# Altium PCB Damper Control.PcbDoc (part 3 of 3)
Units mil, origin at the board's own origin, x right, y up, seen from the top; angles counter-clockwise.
Board outline 4586.61 x 2962.6 mil, 4 copper layers (Top Layer, GND Plane, Power Plane, Bottom Layer), stack 70.356 mil thick; 195 components, 143 nets, 589 pads, 854 vias.
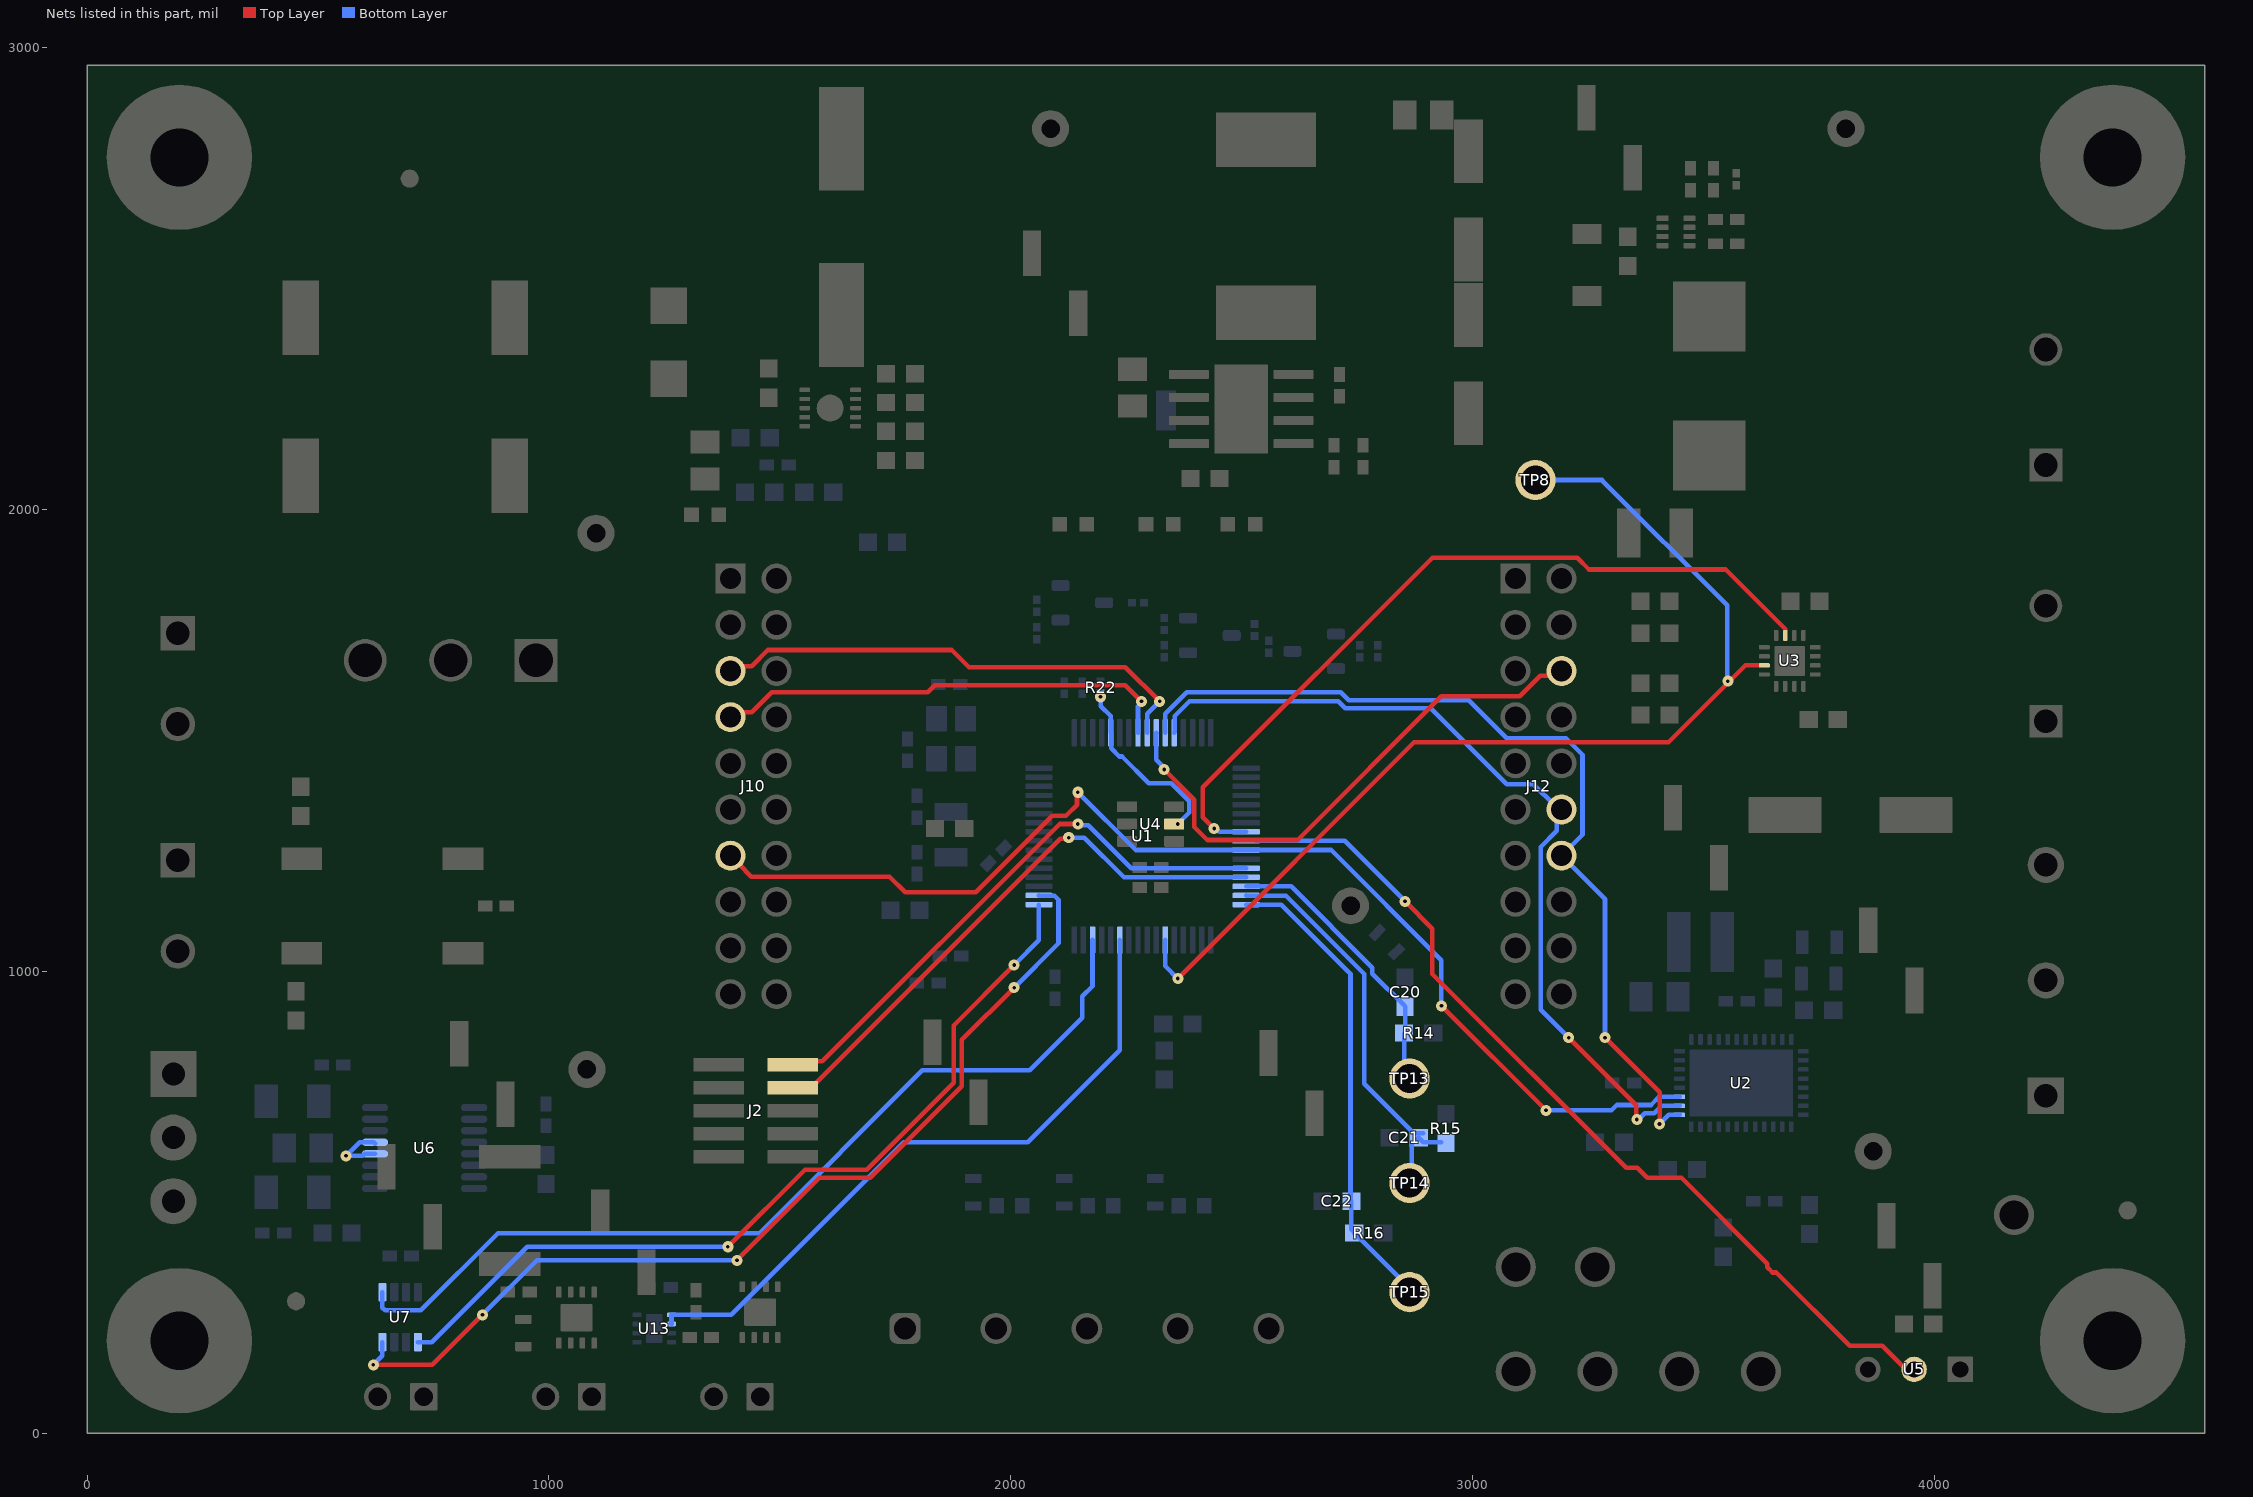
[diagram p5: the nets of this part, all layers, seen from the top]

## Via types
v1: diameter 12, hole 6, Top Layer to Bottom Layer, tented both sides, 463 vias
v2: diameter 24, hole 8, Top Layer to Bottom Layer, tented both sides, 202 vias
v3: diameter 12, hole 6, Top Layer to Bottom Layer, 145 vias
v4: diameter 19.68, hole 7.87, Top Layer to Bottom Layer, 19 vias
v5: diameter 19.68, hole 7.87, Top Layer to Bottom Layer, tented both sides, 16 vias
v6: diameter 24.8, hole 12.99, Top Layer to Bottom Layer, 7 vias
v7: diameter 20, hole 8, Top Layer to Bottom Layer, tented both sides, 1 vias
v8: diameter 24, hole 8, Top Layer to Bottom Layer, 1 vias

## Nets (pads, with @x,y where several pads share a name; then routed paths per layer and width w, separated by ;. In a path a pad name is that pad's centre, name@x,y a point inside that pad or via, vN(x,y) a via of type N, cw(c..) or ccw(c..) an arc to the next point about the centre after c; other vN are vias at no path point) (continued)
S_GND: U6.12 U6.13 | length 140.4
  Bottom Layer w10: U6.13@620.08,629.79 590.42,629.79 v2(561.02,600.39) 597.03,600.39 601.43,604.79 U6.12@623.65,604.79 ; U6.13@620.08,629.92 620.86,629.92 U6.13@623.65,627.13
SHDN: U1.33 U7.5 | length 1853.9
  Top Layer w10: v2(1387.8,403.54) 1554.84,570.59 1688.62,570.59 1876.75,758.72 1876.75,882.65 v2(2007.87,1013.78)
  Bottom Layer w10: U7.5@716.54,196.85 746.56,196.85 953.25,403.54 v2@1387.43,403.54 ; v2@2008.57,1014.48 2061.43,1067.33 U1.33@2061.43,1144.49
SOA: C20.1 R14.2 TP13.1 U1.14 | length 594.9
  Bottom Layer w10: U1.14@2510.25,1183.86 2607.46,1183.86 2783.62,1007.69 2783.62,994.92 C20.1@2853.35,925.2 ; R14.2@2852.36,866.14 2852.36,803.19 2858.31,797.24 TP13.1@2864.17,797.24 ; TP13.1@2854.33,767.72 TP13.1@2856.36,769.75 ; R14.2@2854.33,866.14 C20.1@2854.33,923.23
SOB: C21.1 R15.2 TP14.1 U1.15 | length 897.7
  Bottom Layer w10: U1.15@2510.25,1164.17 2511.15,1163.27 2596.58,1163.27 2765.75,994.09 2765.75,756.89 2873.03,649.61 C21.1@2893.7,649.61 ; TP14.1@2852.55,551.18 TP14.1@2864.17,551.18 ; TP14.1@2874.02,551.18 2869.17,556.02 2869.17,626.06 2882.87,639.76 C21.1@2883.86,639.76 2893.7,629.92 R15.2@2933.07,629.92
SOC: C22.1 R16.2 TP15.1 U1.16 | length 1031.4
  Bottom Layer w10: U1.16@2510.25,1144.49 2585.83,1144.49 2731.3,999.02 2736.22,994.09 C22.1@2736.22,501.97 ; C22.1@2738.19,501.97 2738.19,440.94 R16.2@2746.06,433.07 ; R16.2@2744.09,433.07 2745.08,433.07 2863.19,314.96 TP15.1@2874.02,314.96
SPI1_CLK: J10.13 U1.10 U2.35 | length 2537.2
  Top Layer w10: J10.13@1397.64,1230.32 1399.76,1232.44 1411.26,1232.44 1438.66,1205.04 1737.87,1205.04 1771.65,1171.26 1924.94,1171.26 2090.45,1336.77 2119.98,1336.77 2144,1360.8 2144,1386.13 v2(2145.67,1387.8) ; v2(2933.07,925.2) v2(3159.45,698.82)
  Bottom Layer w10: v2(2145.67,1387.8) 2270.87,1262.6 U1.10@2510.25,1262.6 2694.1,1262.6 2933.07,1023.62 v2(2933.07,925.2) ; v2(3159.45,698.82) 3301.44,698.82 3313.09,710.47 3386.92,710.47 3404.79,728.35 U2.35@3448.82,728.35
SPI1_CS: J12.6 U1.58 | length 1203
  Top Layer w10: v2(2332.68,1437.01) 2398.2,1371.49 2398.2,1312.43 2426.45,1284.18 2621.43,1284.18 2933,1595.75 3102.8,1595.75 3146.93,1639.88 3175.31,1639.88 J12.6@3188.98,1653.54 ; J12.6@3208.66,1653.54 J12.6@3210.24,1651.97
  Bottom Layer w10: U1.58@2316.27,1515.63 U1.58@2315.36,1516.53 2315.36,1457.88 2332.68,1440.57 v2(2332.68,1437.01) ; J12.6@3188.98,1653.54 J12.6@3188.98,1654.72 ; J12.6@3198.82,1653.54 J12.6@3201.97,1650.39
SPI1_MISO: J12.14 U1.59 U2.33 | length 1978
  Top Layer w10: v2(3287.4,856.3) 3405.51,738.19 v2(3405.51,669.29)
  Bottom Layer w10: U1.59@2335.05,1516.53 2335.05,1557.49 2381.89,1604.33 2715.38,1604.33 2732.54,1587.17 2992.39,1587.17 3074.52,1505.04 3202.8,1505.04 3238.66,1469.18 3238.66,1295.75 J12.14@3193.31,1250.39 3287.4,1156.3 v2(3287.4,856.3) ; v2(3405.51,669.29) 3425.2,688.98 U2.33@3448.82,688.98
SPI1_MOSI: J12.12 U1.60 U2.34 | length 1864.4
  Top Layer w10: v2(3208.66,856.3) 3355.04,709.92 3355.04,680.39 v2(3356.3,679.13)
  Bottom Layer w10: U1.60@2354.73,1516.53 2355.64,1517.44 2355.64,1552.8 2387.48,1584.65 2709.78,1584.65 2725.14,1569.29 2910.27,1569.29 3074.52,1405.04 3132.36,1405.04 3179.13,1358.27 J12.12@3188.98,1358.27 ; J12.12@3198.82,1348.43 3195.28,1348.43 J12.12@3193.31,1350.39 3182.79,1339.88 3182.79,1304.02 3147.95,1269.18 3147.95,917.01 v2(3208.66,856.3) ; v2(3356.3,679.13) 3360.09,679.13 3373.55,692.6 3394.32,692.6 3410.39,708.66 U2.34@3448.82,708.66
STB: U1.34 U7.8 | length 2120.6
  Top Layer w10: v2(620.08,147.64) 748.03,147.64 v2(856.3,255.91) ; v2(1407.48,374.02) 1586.18,552.72 1696.02,552.72 1894.62,751.31 1894.62,851.32 v2(2007.87,964.57)
  Bottom Layer w10: v2(620.08,147.64) 639.76,167.32 U7.8@639.76,196.85 ; v2(856.3,255.91) 974.41,374.02 v2(1407.48,374.02) v2@1409.91,374.02 ; v2(2007.87,964.57) 2103.83,1060.52 2103.83,1154.58 2095.15,1163.27 2062.33,1163.27 U1.34@2061.43,1164.17
STEP: TP8.1 U1.22 U3.11 | length 2331.5
  Top Layer w10: v2(2362.2,984.25) 2873.7,1495.75 3424.88,1495.75 3591.53,1662.4 U3.11@3625.46,1662.4
  Bottom Layer w10: U1.22@2335.05,1067.71 2335.05,1011.41 v2(2362.2,984.25) ; TP8.1@3136.51,2063.8 3280.69,2063.8 3551.84,1792.65 3551.84,1629.65 v2(3553.25,1628.24)
STEP_VREF: U1.8 U3.7 | length 1717.1
  Top Layer w10: v2(2440.95,1309.06) 2416.07,1333.93 2416.07,1398.1 2913.72,1895.75 3227.04,1895.75 3252.71,1870.08 3548.72,1870.08 3677.55,1741.25 U3.7@3677.55,1727.36
  Bottom Layer w10: v2(2440.95,1309.06) 2444.73,1309.06 2451.82,1301.97 U1.8@2510.25,1301.97
TCLK: J2.4 U1.13 | length 1214.9
  Top Layer w10: J2.4@1555.12,748.03 1568.7,748.03 2107.36,1286.69 2123.31,1286.69 v2(2125.98,1289.37)
  Bottom Layer w10: v2(2125.98,1289.37) 2159.76,1289.37 2245.59,1203.54 U1.13@2510.25,1203.54
TMAG_INT: R22.1 U1.53 U4.5 | length 407.6
  Bottom Layer w10: R22.1@2194.88,1604.33 2195.44,1603.77 2195.44,1574.24 2216.94,1552.75 U1.53@2216.94,1516.53 2217.84,1515.63 2217.84,1482.81 2235.6,1465.06 2241.37,1465.06 2298.96,1407.48 2348.17,1407.48 2387.08,1368.57 2387.08,1343.77 v2(2362.2,1318.9)
  other v2: 2194.88,1594.49
TMP_IN: U1.9 U5.2 | length 1974.7
  Top Layer w10: v2@2853.36,1152.55 v2(2854.33,1151.57) 2913.39,1092.52 2913.39,994.15 3333.05,574.49 3356.93,574.49 3378.42,552.99 3452.91,552.99 3639,366.91 3639,358.72 3650.06,347.66 3658.24,347.66 3817.07,188.83 3887.87,188.83 3956.69,120 U5.2@3956.69,118.11
  Bottom Layer w10: U1.9@2529.53,1283.19 2530.43,1282.28 2723.62,1282.28 v2(2854.33,1151.57)
TMS: J2.2 U1.12 | length 1237.3
  Top Layer w10: J2.2@1528.35,798.03 1535.15,804.84 1592.24,804.84 2106.3,1318.9 v2(2145.67,1318.9)
  Bottom Layer w10: v2(2145.67,1318.9) 2148.35,1316.22 2168.09,1316.22 2261.08,1223.23 U1.12@2510.25,1223.23
TXD: U1.30 U7.1 | length 1991.5
  Bottom Layer w10: U7.1@639.76,305.12 639.76,271.61 645.62,265.75 722.77,265.75 890.1,433.07 1456.69,433.07 1809.03,785.41 2041.39,785.41 2155.51,899.54 2155.51,946.02 2177.57,968.08 U1.30@2177.57,1067.71
UART_RX: J10.5 U1.57 | length 1077.9
  Top Layer w10: J10.5@1387.8,1653.54 1395.16,1660.91 1439.68,1660.91 1474.52,1695.75 1873.05,1695.75 1910.07,1658.73 2248.75,1658.73 v2(2322.83,1584.65)
  Bottom Layer w10: U1.57@2295.68,1516.53 2295.68,1557.49 v2(2322.83,1584.65)
UART_TX: J10.7 U1.56 | length 1009.1
  Top Layer w10: J10.7@1387.8,1555.12 1393.59,1560.91 1439.68,1560.91 1483.1,1604.33 1820.87,1604.33 1835.9,1619.36 2248.75,1619.36 v2(2283.46,1584.65)
  Bottom Layer w10: U1.56@2276.9,1517.44 U1.56@2275.99,1516.53 2275.99,1573.39 2283.46,1580.86 v2(2283.46,1584.65)
V_Ctrl: U1.27 U13.1 U13.2 | length 1468.5
  Bottom Layer w10: U13.2@1265.75,236.22 U13.1@1265.75,255.83 ; U13.1@1265.75,255.91 1395.04,255.91 1769.06,629.92 2037.4,629.92 2125.98,718.5 ; 2124.57,717.09 2236.62,829.14 U1.27@2236.62,1067.71
pads on no net: FID1.1 FID2.1 FID3.1 H2.0 H3.1 H5.0 H6.1 H8.0 H9.1 H11.0 H12.1 J2.6 J2.8 J10.3 J10.6 J10.8 J10.9 J10.10 J10.11 J10.12 J10.14 J10.15 J10.16 J10.18 J10.20 J12.1 J12.3 J12.4 J12.5 J12.7 J12.8 J12.9 J12.10 J12.11 J12.13 J12.15 J12.16 J12.18 J12.20 U1.21 U1.47 U1.54 U1.61 U2.1 U2.24 U6.6 U6.7 U8.6 U9.1 U9.2 U11.9 U12.9 U13.9@1228.35,208.66 U13.9@1228.35,244.09
copper on no net:
  other v4: 1060.04,230.32 1457.68,242.13 1035.43,250 1084.65,250 1433.07,261.81 1482.28,261.81 1060.04,269.68 1457.68,281.5

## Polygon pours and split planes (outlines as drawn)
NetC31_2 on Bottom Layer "BOTTOM_LAYER_NETC31_2_P001" (solid, remove dead copper, pour order 1): 2372.05,2263.78 2363.57,2263.78 2204.72,2263.78 2204.72,2322.83 2076.77,2322.83 2076.77,2125.98 2372.05,2125.98
GND on Bottom Layer "BOTTOM_LAYER_GND_P119" (solid, remove dead copper, pour order 119): -27.96,2927.62 -27.96,4.39 -47.65,-15.29 -27.96,-34.98 4568.49,-34.98 4568.49,2917.78 4558.65,2927.62
NetL1_1 on Bottom Layer "BOTTOM_LAYER_NETL1_1_P073" (solid, remove dead copper, pour order 73): 3515.59,954.72 3614.02,954.72 3614.02,1029.69 3622.05,1029.69 3622.05,1147.8 3515.59,1147.8 3515.59,990.32
5V on Bottom Layer "BOTTOM_LAYER_5V_P076" (solid, remove dead copper, pour order 76): 3484.25,905.51 3484.25,1151.57 3395.67,1151.57 3395.67,994.09 3405.51,994.09 3405.51,885.83 3503.94,885.83 3503.94,905.51
OUTB on Bottom Layer "BOTTOM_LAYER_OUTB_P003" (solid, remove dead copper, pour order 3): 4576.77,1082.68 4576.77,836.61 4183.07,836.61 4084.65,738.19 3710.63,738.19 3710.63,787.4 4005.91,787.4 4222.44,1082.68
NetC29_1 on Bottom Layer "BOTTOM_LAYER_NETC29_1_P005" (solid, remove dead copper, pour order 5): 816.93,688.98 816.93,669.29 885.83,669.29 885.83,659.45 964.57,659.45 964.57,580.71 1013.78,580.71 1013.78,688.98 935.04,688.98 935.04,718.5 875.98,718.5 875.98,688.98
Line on Bottom Layer "BOTTOM_LAYER_LINE_P011" (solid, remove dead copper, pour order 11): 9.84,1574.8 521.65,1574.8 521.65,1830.71 501.97,1850.39 9.84,1850.39
Neutral on Bottom Layer "BOTTOM_LAYER_NEUTRAL_P031" (solid, remove dead copper, pour order 31): 9.84,1574.8 521.65,1574.8 521.65,1328.74 9.84,1328.74
EFuse_IN on Bottom Layer "BOTTOM_LAYER_EFUSE_IN_P051" (solid, remove dead copper, pour order 51): 1387.95,2193.43 1387.95,2017.88 1387.8,2017.72 1338.58,2017.72 1338.58,1958.66 1456.69,1958.66 1456.69,2066.93 1446.85,2066.93 1446.85,2253.94 1387.8,2253.94
F_IN1 on Bottom Layer "BOTTOM_LAYER_F_IN1_P052" (solid, remove dead copper, pour order 52): 111.73,838.73 108.27,835.27 108.27,718.5 305.12,718.5 305.12,659.45 413.39,659.45 413.39,767.72 413.39,836.61 118.11,836.61
F_IN2 on Bottom Layer "BOTTOM_LAYER_F_IN2_P053" (solid, remove dead copper, pour order 53): 108.27,698.82 108.27,690.17 108.27,580.71 265.75,580.71 265.75,472.44 413.39,472.44 413.39,561.02 354.33,561.02 354.33,659.45 295.28,659.45 295.28,718.5 108.27,718.5
NetC12_2 on Bottom Layer "Bottom Layer-NetC12_2" (solid, remove dead copper, pour order 54): 3622.05,836.61 3681.1,836.61 3681.1,875.98 3759.84,875.98 3759.84,1033.46 3986.22,1033.46 3986.22,1279.53 3631.89,1279.53 3631.89,984.25 3681.1,984.25 3681.1,905.51 3651.57,905.51 3651.57,885.83 3622.05,885.83
OUTA on Bottom Layer "BOTTOM_LAYER_OUTA_P055" (solid, remove dead copper, pour order 55): 4576.77,1348.43 4084.65,1348.43 4084.65,1141.73 3986.22,1141.73 3986.22,846.46 3710.63,846.46 3710.63,797.24 4005.91,797.24 4291.34,1082.68 4576.77,1082.68
F_GND on Bottom Layer "BOTTOM_LAYER_F_GND_P096" (solid, remove dead copper, pour order 96): 76.51,849.79 78.74,847.56 78.74,378.94 688.98,378.94 688.98,418.31 688.98,880.91 78.74,880.91
NetC4_1 on Bottom Layer "BOTTOM_LAYER_NETC4_1_P090" (solid, remove dead copper, pour order 90): 2012.8,1264.76 1968.5,1309.06 1924.21,1264.76 1968.5,1220.47
PGND on Bottom Layer "BOTTOM_LAYER_PGND_P081" (solid, remove dead copper, pour order 81): 3681.1,1092.52 3897.64,1092.52 3897.64,846.46 3681.1,846.46
OUTC on Bottom Layer "BOTTOM_LAYER_OUTC_P056" (solid, remove dead copper, pour order 56): 4576.77,836.61 4576.77,590.55 4084.65,590.55 4015.75,659.45 3710.63,659.45 3710.63,728.35 4074.8,728.35 4183.07,836.61
GND on Top Layer "TOP_LAYER_GND_P124" (solid, remove dead copper, pour order 124): 0,2972.44 9.84,2962.6 4586.61,2962.6 4586.61,2470.47 3730.32,2470.47 3720.47,2480.32 3602.36,2480.32 3602.36,2588.58 3592.52,2598.43 3582.68,2588.58 3444.88,2588.58 3444.88,2529.53 3405.51,2529.53 3405.51,2490.16 3297.24,2490.16 3297.24,2293.31 3730.32,2293.31 3730.32,2470.47 4586.61,2470.47 4586.61,0 4576.77,-9.84 0,-9.84
EFuse_IN on Top Layer "TOP_LAYER_EFUSE_IN_P008" (solid, remove dead copper, pour order 8): 716.69,1548.48 872.78,1548.48 875.98,1545.28 875.98,1811.02 1309.06,1811.02 1309.06,2175.2 1476.38,2175.2 1525.59,2224.41 1564.96,2224.41 1564.96,2273.62 1358.27,2273.62 1358.27,2352.36 1141.73,2352.36 1141.73,2234.25 19.68,2234.25 19.68,1840.55 718.5,1840.55
Line on Top Layer "TOP_LAYER_LINE_P043" (solid, remove dead copper, pour order 43): 29.53,1131.89 639.76,1131.89 639.76,935.04 29.53,935.04
Neutral on Top Layer "TOP_LAYER_NEUTRAL_P064" (solid, remove dead copper, pour order 64): 29.53,1368.11 639.76,1368.11 639.76,1141.73 29.53,1141.73
NetC35_1 on Top Layer "TOP_LAYER_NETC35_1_P067" (solid, remove dead copper, pour order 67): 649.61,1102.36 649.61,954.72 1033.46,954.72 1033.46,964.57 1033.46,1801.18 885.83,1801.18 885.83,1102.36
24VDC_IN on Top Layer "TOP_LAYER_24VDC_IN_P068" (solid, remove dead copper, pour order 68): 39.37,1830.71 39.37,1614.17 708.66,1614.17 708.66,1830.71
15VDC on Top Layer "Top Layer-15VDC" (solid, remove dead copper, pour order 69): 2746.06,2116.14 2952.76,2116.14 2952.76,2303.15 3198.82,2303.15 3198.82,2805.12 3277.56,2805.12 3277.56,2942.91 3100.39,2942.91 3100.39,2677.17 2952.76,2677.17 2952.76,2883.86 2303.15,2883.86 2303.15,2588.58 2746.06,2588.58
NetC36_1 on Top Layer "TOP_LAYER_NETC36_1_P110" (solid, remove dead copper, pour order 110): 2440.95,2490.16 2440.95,2342.52 2568.9,2342.52 2568.9,2273.62 2736.22,2273.62 2736.22,2490.16
3V3 on Top Layer "TOP_LAYER_3V3_P101" (solid, remove dead copper, pour order 101): 629.92,629.92 629.92,531.5 708.66,531.5 708.66,629.92
NetC30_1 on Top Layer "TOP_LAYER_NETC30_1_P104" (solid, remove dead copper, pour order 104): 767.72,501.97 688.98,501.97 688.98,374.02 767.72,374.02
NetC31_2 on Top Layer "Top Layer-NetC31_2" (solid, remove dead copper, pour order 83): 1938.98,2116.14 2224.41,2116.14 2224.41,2135.83 2312.99,2135.83 2312.99,2175.2 2431.1,2175.2 2431.1,2263.78 2204.72,2263.78 2204.72,2372.05 2204.72,2618.11 2096.46,2618.11 2096.46,2431.1 2093.14,2430.78 1978.67,2430.78 1978.35,2431.1 1978.35,2332.68 1938.98,2332.68
EFuse_OUT on Top Layer "Top Layer-EFuse_OUT" (solid, remove dead copper, pour order 123): 1397.64,2253.94 1673.23,2253.94 1673.23,2322.83 1978.35,2322.83 1978.35,2431.1 2106.3,2431.1 2106.3,2618.11 1397.64,2618.11
BOUT1 on Top Layer "TOP_LAYER_BOUT1_P107" (solid, remove dead copper, pour order 107): 4576.77,2470.47 4094.49,2470.47 4094.49,2244.09 3769.69,1751.97 3769.69,1702.76 3789.37,1702.76 4291.34,2214.57 4576.77,2214.57
0_10VDC on Top Layer "TOP_LAYER_0_10VDC_P122" (solid, remove dead copper, pour order 122): 1486.22,39.37 1486.22,187.01 1505.91,187.01 1505.91,216.54 1338.58,216.54 1338.58,187.01 1427.17,187.01 1427.17,39.37
4_20mA on Top Layer "TOP_LAYER_4_20MA_P121" (solid, remove dead copper, pour order 121): 1122.05,206.69 1122.05,19.68 1053.15,19.68 1053.15,177.17 915.35,177.17 915.35,206.69
NetC26_1 on Top Layer "TOP_LAYER_NETC26_1_P120" (solid, remove dead copper, pour order 120): 2578.74,875.98 2549.21,905.51 2322.83,905.51 2244.09,984.25 2244.09,1141.73 2352.36,1141.73 2352.36,1171.26 2214.57,1171.26 2214.57,944.88 2312.99,846.46 2519.69,846.46 2519.69,797.24 2539.37,777.56 2578.74,777.56
NetC28_1 on Top Layer "TOP_LAYER_NETC28_1_P118" (solid, remove dead copper, pour order 118): 4045.28,374.02 4045.28,285.43 4084.65,285.43 4084.65,88.58 4025.59,88.58 4025.59,167.32 3976.38,167.32 3976.38,285.43 3848.43,285.43 3848.43,374.02 3858.27,374.02
AOUT1 on Top Layer "TOP_LAYER_AOUT1_P116" (solid, remove dead copper, pour order 116): 4591.05,1610.21 4586.61,1605.77 4586.61,1377.95 4074.8,1377.95 3877.95,1574.8 3818.9,1574.8 3769.69,1624.02 3769.69,1633.86 3838.58,1633.86 3838.58,1624.02 4575.59,1624.02
AOUT2 on Top Layer "TOP_LAYER_AOUT2_P115" (solid, remove dead copper, pour order 115): 4576.77,1929.13 4183.07,1929.13 4183.07,1919.29 3937.01,1673.23 3769.69,1673.23 3769.69,1633.86 3838.58,1633.86 3838.58,1624.02 4576.77,1624.02
BOUT2 on Top Layer "TOP_LAYER_BOUT2_P105" (solid, remove dead copper, pour order 105): 4576.77,2214.57 4281.5,2214.57 3799.21,1702.76 3769.69,1702.76 3769.69,1673.23 3937.01,1673.23 4192.91,1929.13 4576.77,1929.13
NetC10_2 on Top Layer "Top Layer-NetC10_2" (solid, remove dead copper, pour order 109): 3759.84,1161.42 3759.84,1559.06 3710.63,1598.43 3710.63,1628.52 3690.95,1628.52 3690.95,1574.8 3582.68,1574.8 3582.68,1289.37 3356.3,1289.37 3356.3,1161.42 3582.68,1161.42
NetC26_1 on Top Layer "TOP_LAYER_NETC26_1_P113" (solid, remove dead copper, pour order 113): 2335.23,1376.9 2332.68,1374.35 2332.68,1259.84 2312.99,1240.16 2312.99,1151.57 2352.36,1151.57 2352.36,1250 2362.2,1250 2372.05,1259.84 2372.05,1377.95 2332.68,1377.95
NetC43_1 on Top Layer "TOP_LAYER_NETC43_1_P098" (solid, remove dead copper, pour order 98): 3395.67,2559.06 3205.87,2559.06 3205.87,2834.65 3395.67,2834.65
3V3 on Top Layer "TOP_LAYER_3V3_P112" (solid, remove dead copper, pour order 112): 3297.24,2293.31 3297.24,2037.4 3395.67,2037.4 3395.67,1889.76 3720.47,1889.76 3730.32,1889.76 3730.32,2293.31
NetC46_1 on Top Layer "TOP_LAYER_NETC46_1_P085" (solid, remove dead copper, pour order 85): 3454.72,2588.58 3454.72,2519.69 3405.51,2519.69 3405.51,2490.16 3405.51,2332.68 3602.36,2332.68 3602.36,2500 3602.36,2519.69 3553.15,2519.69 3484.25,2519.69 3484.25,2588.58
NetC36_2 on Top Layer "TOP_LAYER_NETC36_2_P111" (solid, remove dead copper, pour order 111): 2568.9,2224.41 2677.17,2224.41 2736.22,2224.41 2736.22,2263.78 2568.9,2263.78
GND on Power Plane "POWER_PLANE_GND_P133" (solid, remove dead copper, pour order 133): 29.53,1840.55 29.53,2942.91 2312.99,2942.91 2312.99,2312.99 1141.73,2312.99 1141.73,2244.09 246.06,2244.09 246.06,1840.55
GND on Power Plane "POWER_PLANE_GND_P130" (solid, remove dead copper, pour order 130): 649.61,1112.2 875.98,1112.2 875.98,1545.28 708.66,1545.28 708.66,1604.33 19.68,1604.33 19.68,1377.95 649.61,1377.95
GND on Power Plane "POWER_PLANE_GND_P134" (solid, remove dead copper, pour order 134): 19.68,954.72 19.68,885.83 1328.74,885.83 1328.74,1811.02 1033.46,1811.02 1033.46,954.72
EFuse_IN on Power Plane "POWER_PLANE_EFUSE_IN_P028" (solid, remove dead copper, pour order 28): 717.5,1541.77 721.01,1545.28 875.98,1545.28 875.98,1811.02 1309.06,1811.02 1309.06,2175.2 1368.11,2175.2 1368.11,2352.36 1141.73,2352.36 1141.73,2234.25 246.06,2234.25 246.06,1840.55 718.5,1840.55
NetC35_1 on Power Plane "POWER_PLANE_NETC35_1_P132" (solid, remove dead copper, pour order 132): 649.61,1102.36 649.61,954.72 1033.46,954.72 1033.46,1801.18 885.83,1801.18 885.83,1102.36
24VDC_IN on Power Plane "POWER_PLANE_24VDC_IN_P131" (solid, remove dead copper, pour order 131): 19.68,1830.71 19.68,1614.17 708.66,1614.17 708.66,1830.71
Neutral on Power Plane "POWER_PLANE_NEUTRAL_P129" (solid, remove dead copper, pour order 129): 29.53,1368.11 29.53,1141.73 639.76,1141.73 639.76,1368.11
Line on Power Plane "POWER_PLANE_LINE_P128" (solid, remove dead copper, pour order 128): 19.68,1131.89 19.26,954.72 639.76,954.72 639.76,1131.89
3V3 on Power Plane "Power Plane-3V3" (solid, remove dead copper, pour order 127): 4586.61,0 4586.61,501.97 3769.69,501.97 3769.69,2312.99 1328.74,2312.99 1328.74,895.67 0,895.67 0,9.84 -9.84,0
NetC4_1 on Power Plane "POWER_PLANE_NETC4_1_P033" (solid, remove dead copper, pour order 33): 1781.5,1259.84 1781.5,1062.99 2032.48,1062.99 2027.43,1325.38 1929.13,1259.84
15VDC on Power Plane "Power Plane-15VDC" (solid, remove dead copper, pour order 126): 2312.99,2322.83 2746.06,2322.83 2746.06,2066.93 2982.28,2066.93 2982.28,2322.83 3750,2322.83 3750,1732.28 3257.87,1732.28 3257.87,492.13 4586.61,492.13 4586.61,2952.76 2312.99,2952.76
EFuse_OUT on Power Plane "POWER_PLANE_EFUSE_OUT_P077" (solid, remove dead copper, pour order 77): 2099.28,2622.48 2096.46,2619.66 2096.46,2322.83 1397.64,2322.83 1397.64,2637.8 2096.46,2637.8 2096.46,2618.11
GND on GND Plane "GND_PLANE_GND_P093" (solid, remove dead copper, pour order 93): 0,2972.44 0,9.84 9.84,0 4586.61,0 4586.61,2962.6
F_GND on GND Plane "GND_PLANE_F_GND_P091" (solid, remove dead copper, pour order 91): 29.53,885.83 29.53,383.86 688.98,383.86 688.98,885.83
S_GND on GND Plane "GND_PLANE_S_GND_P080" (solid, remove dead copper, pour order 80): 575.79,571.17 575.79,659.45 487.2,659.45 487.2,570.56 575.79,570.56
PGND on GND Plane "GND_PLANE_PGND_P089" (solid, remove dead copper, pour order 89): 3779.53,875.98 3681.1,875.98 3681.1,551.18 4094.49,551.18 4094.49,1033.46 3779.53,1033.46 3779.53,1023.62 3779.53,1033.46 3779.53,1023.62

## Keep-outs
Keep-Out Layer:
  text ".Layer_Name" at 577,-858.49 h60

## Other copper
Top Layer:
  pour cut-out: 2303.15,2578.74 2303.15,2362.2 2431.1,2362.2 2431.1,2500 2736.22,2500 2736.22,2578.74
  text ".Layer_Name" at 577,-858.49 h60
GND Plane:
  pour cut-out: 2017.72,1328.74 2086.61,1328.74 2086.61,1309.06 2027.56,1309.06 2017.72,1318.9
  pour cut-out: 1879.92,1161.42 2032.48,1313.98 2017.72,1328.74 1850.39,1161.42
  pour cut-out: 1988.19,1643.7 1968.5,1643.7 1968.5,1486.22 2037.4,1417.32 2037.4,1437.01 1988.19,1486.22
  pour cut-out: 1751.97,1181.1 1870.08,1181.1 1870.08,1161.42 1751.97,1161.42
  pour cut-out: 1751.97,1643.7 1751.97,1161.42 1732.28,1161.42 1732.28,1643.7
  pour cut-out: 1732.28,1643.7 1988.19,1643.7 1988.19,1663.39 1732.28,1663.39
Bottom Layer:
  pour cut-out: 1830.71,1328.74 1830.71,1279.53 1929.13,1279.53 1988.19,1338.58 1978.35,1348.43 1958.66,1328.74
  text ".Layer_Name" at 577,-858.49 h60

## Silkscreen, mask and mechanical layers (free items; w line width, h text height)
Top Overlay:
  lines w10: 1417.32,1594.49 1437.01,1614.17 1545.28,1614.17 ; 1427.17,1683.07 1446.85,1702.76 1545.28,1702.76 ; 3041.34,1082.68 3051.18,1082.68 3061.02,1072.83 ; 3228.35,1250 3287.4,1250 3297.24,1240.16 3297.24,1220.47 ; 3228.35,1368.11 3267.72,1407.48 ; 3228.35,1624.02 3267.72,1584.65 3267.72,1515.75 ; 3267.72,1417.32 3267.72,1407.48 ; 3267.72,1407.48 3267.72,1407.48
  text "TPS62932 VIN" at 3293.4,2880.02 h30
  text "GND" at 2043.4,2732.38 h30
  text "GND" at 3765.84,2732.38 h30
  text "EFuse_OUT" at 1944.98,2333.83 h30
  text "BOUT1" at 4049.12,2309.15 h30 r90
  text "BOUT2" at 4049.12,2053.24 h30 r90
  text "STEP" at 3076.87,1944.98 h30
  text "EFuse_IN" at 990.25,1861.39 h30
  text "3V3" at 1246.16,1836.71 h30
  text "5V" at 1561.12,1836.71 h30
  text "GND" at 3254.03,1836.71 h30
  text "GND" at 1561.12,1738.28 h30
  text "AOUT2" at 4049.12,1738.28 h30 r90
  text "UART_RX" at 1561.12,1674.38 h30
  text "24VDC_IN" at 412.23,1620.17 h30 r90
  text "UART_TX" at 1561.12,1595.64 h30
  text "'.PRJ_Number'.PCB_Rev" at 2007.87,1515.75 h108.27
  text "24VDC" at 547.34,1492.22 h30
  text "24VAC" at 901.67,1492.22 h30
  text "AOUT1" at 4049.12,1482.38 h30 r90
  text "SPI1_CS" at 3263.87,1477.53 h30
  text "GND" at 407.39,1472.54 h30 r90
  text "SPI1_MOSI" at 3263.87,1428.32 h30
  text "24VAC IN" at 124.11,1354.43 h30
  text "SPI1_CLK" at 1098.52,1231.47 h30
  text "SPI1_MISO" at 3263.87,1182.26 h30
  text "OUTA" at 4049.12,1157.57 h30 r90
  text "Neutral" at 397.54,1147.73 h30 r90
  text "GPIO1" at 2899.7,1068.99 h30
  text "I2C1_SCL" at 1098.52,1034.62 h30
  text "Line" at 397.54,970.57 h30 r90
  text "GPIO2" at 2899.7,950.88 h30
  text "I2C1_SDA" at 1098.52,926.35 h30
  text "OUTB" at 4049.12,921.35 h30 r90
  text "MSPM0 VDD" at 1757.97,901.67 h30
  text "TMAG VCC" at 2496.16,881.98 h30
  text "DRV8316C VM" at 3706.79,862.3 h30
  text "GND" at 1039.46,852.46 h30
  text "3V3" at 1196.94,783.56 h30
  text "TMS" at 1610.33,783.56 h30
  text "F_IN1" at 333.49,744.19 h30 r90
  text "GND" at 1196.94,734.35 h30
  text "TCLK" at 1610.33,734.35 h30
  text "ISO1212 VCC" at 557.18,685.13 h30
  text "GND" at 1196.94,685.13 h30
  text "OUTC" at 4049.12,685.13 h30 r90
  text "SOA" at 2820.96,655.61 h30
  text "GND" at 1196.94,635.92 h30
  text "GND" at 1196.94,586.71 h30
  text "RESET" at 1610.33,586.71 h30
  text "F_IN2" at 333.49,567.02 h30 r90
  text "PGND" at 3815.06,517.81 h30
  text "TLV9002 VCC" at 1147.73,488.28 h30
  text "GND" at 1738.28,458.76 h30
  text "HALLC" at 1895.76,458.76 h30
  text "HALLB" at 2092.61,458.76 h30
  text "HALLA" at 2289.46,458.76 h30
  text "3V3" at 2506,458.76 h30
  text "INLC" at 3037.5,439.07 h30
  text "INHC" at 3214.66,439.07 h30
  text "SOB" at 2820.96,429.23 h30
  text "F_GND" at 333.49,389.86 h30 r90
  text "TMP VIN" at 3628.05,370.17 h30
  text "FAULT" at 4100.49,360.33 h30
  text "TCAN VCC" at 547.34,350.49 h30
  text "SOC" at 2830.8,183.17 h30
  text "4_20mA" at 1039.46,148.79 h30
  text "0_10VDC" at 1413.48,148.79 h30
  text "CANH" at 557.18,143.8 h30
  text "CANL" at 704.82,143.8 h30
  text "GND" at 941.04,143.8 h30
  text "GND" at 1295.37,143.8 h30
  text "INLB" at 3037.5,15.84 h30
  text "INHB" at 3214.66,15.84 h30
  text "INLA" at 3391.83,15.84 h30
  text "INHA" at 3568.99,15.84 h30
  text ".Layer_Name" at 577,-858.49 h60
Bottom Overlay:
  text ".Layer_Name" at 577,-858.49 h60
Top Paste:
  text ".Layer_Name" at 577,-858.49 h60
Bottom Paste:
  text ".Layer_Name" at 577,-858.49 h60
Top Solder:
  text ".Layer_Name" at 577,-858.49 h60
  text ".Layer_Name" at 577,-858.49 h60
Bottom Solder:
  text ".Layer_Name" at 577,-858.49 h60
Drill Guide:
  text ".Layer_Name" at 577,-858.49 h60
M1 Board Outline:
  the board outline again, w10
  text ".Layer_Name" at 577,-858.49 h60
M2 Board Dimensions:
  rectangle: 0,-275 125,-150
  rectangle: 125,-400 500,-275
  lines w7: 0,-275 1000,-275 ; 125,-400 125,-150 ; 250,-400 250,-150 ; 500,-400 500,-150 ; 750,-400 750,-150 ; 0,-400 1000,-400 1000,-150 0,-150 0,-400
  text ".Layer_Name" at 577,-858.49 h60
M3 3D STEP Top:
  text ".Layer_Name" at 577,-858.49 h60
M4 3D STEP Bottom:
  text ".Layer_Name" at 577,-858.49 h60
M5 Assembly Top:
  lines w10: -292,-930.17 6308,-930.17 ; -292,-726.83 6310,-726.83 ; -292,-523.5 -292,-1133.5 3713,-1133.5 6310,-1133.5 6310,-523.5 -291.5,-523.5 -291.5,-1133.5 1284,-1133.5 ; 2173,-1133.5 2173,-523.5 ; 3440,-726.83 3440,-523.5 ; 4280,-726.83 4280,-523.5 ; 4902,-1140 4902,-937.17
  text "COMPONENTS MARKED 'DNP' SHOULD NOT BE POPULATED." at 1153.5,-318.5 h60
  text "ASSEMBLY VARIANT:" at 1153,-434 h60
  text ".VariantName" at 2189,-434 h60
  text "PCB VIEWED FROM TOP SIDE" at -228.5,-655.67 h60
  text "BOARD #:" at 2248,-655.67 h60
  text ".PRJ_Number" at 2793.5,-655.67 h60
  text "REV:" at 3638,-655.67 h60
  text ".PCB_Rev" at 3929.5,-655.67 h60
  text "SVN REV:" at 4476,-655.67 h60
  text ".VersionControl_RevNumber" at 4982,-655.67 h60
  text "TID #:" at 2248,-859 h60
  text ".TID" at 2793.5,-859 h60
  text "PLOT NAME =" at -228.5,-1064.34 h60
  text ".plot_File_Name" at 577,-1064.34 h60
  text "GENERATED    :" at 2250,-1064.34 h60
  text ".Print_Date" at 3119.5,-1064.34 h60
  text ".Print_Time" at 3848.5,-1064.34 h60
  text "TEXAS INSTRUMENTS" at 5113,-1064.34 h60
M6 Assembly Bottom:
  lines w10: -292.5,-727.33 6309.5,-727.33 ; -290.5,-930.67 6309.5,-930.67 ; 1115.5,-1140.5 1115.5,-937.67 ; 1737.5,-727.33 1737.5,-524 ; 2577.5,-727.33 2577.5,-524 ; 3844.5,-1134 3844.5,-524 ; 4733.5,-1134 6309,-1134 6309,-524 -292.5,-524 -292.5,-1134 2304.5,-1134 6309.5,-1134 6309.5,-524
  text "COMPONENTS MARKED 'DNP' SHOULD NOT BE POPULATED." at 6102,-318 h60
  text ".VariantName" at 5058,-434 h60
  text "ASSEMBLY VARIANT:" at 6097,-434 h60
  text ".VersionControl_RevNumber" at 1035.5,-656.17 h60
  text "SVN REV:" at 1541.5,-656.17 h60
  text ".PCB_Rev" at 2088,-656.17 h60
  text "REV:" at 2379.5,-656.17 h60
  text ".PRJ_Number" at 3224,-656.17 h60
  text "BOARD #:" at 3769.5,-656.17 h60
  text "PCB VIEWED FROM BOTTOM SIDE" at 6246,-656.17 h60
  text ".TID" at 3224,-859.5 h60
  text "TID #:" at 3769.5,-859.5 h60
  text "TEXAS INSTRUMENTS" at 904.5,-1064.84 h60
  text ".Print_Time" at 2169,-1064.84 h60
  text ".Print_Date" at 2898,-1064.84 h60
  text "GENERATED    :" at 3767.5,-1064.84 h60
  text ".plot_File_Name" at 5440.5,-1064.84 h60
  text "PLOT NAME =" at 6246,-1064.84 h60
M9 Title Sheet:
  drawing of 57 lines, arcs and shapes, not listed
  text "1" at 739.84,8036.5 h70
  text "2" at 3235.5,8036.5 h70
  text "3" at 5724.84,8036.5 h70
  text "4" at 8231.51,8036.5 h70
  text "5" at 10730.5,8036.5 h70
  text "6" at 13235.5,8036.5 h70
  text "A" at -416.5,6893.5 h70
  text "A" at 14383.5,6893.5 h70
  text "B" at -416.5,4513.5 h70
  text "B" at 14383.5,4513.5 h70
  text "C" at -416.5,2138.5 h70
  text "C" at 14383.5,2138.5 h70
  text "PROJECT TITLE:" at 11343.5,277.5 h45
  text ".PRJ_Title" at 11393.5,144.17 h70
  text "DESIGNED FOR:" at 11343.5,-23.5 h45
  text ".PRJ_Customer" at 11393.5,-163.5 h70
  text "D" at -416.5,-231.5 h70
  text "D" at 14383.5,-231.5 h70
  text "FILE NAME:" at 11343.5,-323.5 h45
  text ".PCB_File_Name_No_Path" at 11393.5,-443.5 h70
  text "Texas Instruments (TI) and/or its licensors do not warrant the accuracy or completeness of this specification" at 6374,-605.34 h45
  text "ENGINEER:" at 11343.5,-613.5 h45
  text "LAYOUT BY:" at 12848.5,-613.5 h45
  text "or any information contained therein. TI and/or its licensors do not warrant that this design will meet" at 6329.01,-718 h45
  text ".PRJ_Engineer" at 11393.5,-768.49 h70
  text ".PCB_Layout" at 12899,-768.49 h70
  text "the specifications, will be suitable for your application or fit for any particular purpose, or will operate in" at 6329.01,-830.67 h45
  text ".Layer_Name" at 577,-858.49 h60
  text "ALTIUM DESIGNER VERSION:" at 12848.5,-923.5 h45
  text "an implementation. TI and/or its licensors do not warrant that the design is production worthy. You should" at 6329.01,-943.33 h45
  text "completely validate and test your design implementation to confirm the system functionality for your application." at 6374,-1056 h45
  text ".print_Scale" at 11393.5,-1056.83 h70
  text ".Application_BuildNumber" at 12899,-1056.83 h70
  text "1" at 739.84,-1263.5 h70
  text "2" at 3235.5,-1263.5 h70
  text "3" at 5724.84,-1263.5 h70
  text "4" at 8231.51,-1263.5 h70
  text "5" at 10730.5,-1263.5 h70
  text "6" at 13235.5,-1263.5 h70
M10 Fab Notes:
  drawing of 189 lines, arcs and shapes, not listed
  text "DESIGN INFORMATION" at 12382.02,6356.17 h60
  text "MIN. TRACK WIDTH:" at 11737.46,6224.05 h60
  text "8" at 12833.7,6224.05 h60
  text "MIL" at 12988.46,6224.05 h60
  text "7.874" at 12667.32,6102.36 h60
  text "MIN. CLEARANCE:" at 11737.46,6099.92 h60
  text "MIL" at 12988.46,6099.92 h60
  text "MIN. VIA PAD SIZE:" at 11737.46,5975.8 h60
  text "24" at 12803.71,5975.8 h60
  text "MIL" at 12988.46,5975.8 h60
  text "0.05mm (2MIL)" at 12432.46,5845.9 h60
  text "MINIMUM ANNULAR RING" at 11408.23,5837.67 h60
  text "EXTERNAL" at 13140.46,5837.67 h60
  text "PER" at 11608.23,5727.55 h60
  text "IPC-D-275 CLASS 2 LEVEL C" at 11828.23,5727.54 h60
  text "MIL, HOLES" at 13316.46,5627.07 h60
  text "+/-" at 12924,5618.48 h60
  text "+/-" at 13778,5618.48 h60
  text "REGISTRATION TOLERANCES:" at 11408.23,5617.42 h60
  text "METAL" at 12608,5617.42 h60
  text "5" at 13184.2,5617.42 h60
  text "3" at 14017.2,5617.42 h60
  text "MIL" at 14133.46,5617.42 h60
  text "HOLE SIZE TOLERANCE (UNLESS OTHERWISE SPECIFIED):" at 11408.23,5519.1 h60
  text "+/-" at 13778,5516.23 h60
  text "3" at 14017.2,5515.17 h60
  text "MIL" at 14133.46,5515.17 h60
  text "MATERIAL:" at 11333.46,5377.52 h60
  text "FR-4 High Tg" at 12319.9,5249 h60
  text "X" at 12175.46,5241.01 h60
  text "FR-4" at 11754.46,5236.49 h60
  text "OTHER" at 13242.46,5236.49 h60
  text "62 MIL (1.6mm) +/-10%" at 12074.56,5093.46 h60
  text "X" at 11954.46,5091.01 h60
  text "THICKNESS:" at 11408.23,5085.24 h60
  text "OTHER" at 13359.46,5085.24 h60
  text "TOLERANCE:" at 11408.23,4946.92 h60
  text "X" at 12256.46,4946.92 h60
  text "ANSI IPC-6012 TYPE 3 CLASS 2" at 12434.48,4946.92 h60
  text "OTHER +/-" at 12434.46,4802.73 h60
  text "BOW & TWIST:" at 11408.23,4657.54 h60
  text "X" at 12256.46,4657.54 h60
  text "ANSI IPC-6012 TYPE 3 CLASS 2" at 12434.48,4657.54 h60
  text "OTHER +/-" at 12434.46,4510.85 h60
  text "DRILLING:" at 11333.46,4380.23 h60
  text "NC_DRILL FILES" at 13094.46,4275.04 h60
  text "REFERENCE:" at 11408.23,4271.1 h60
  text "X" at 12065.46,4271.01 h60
  text "AS SHOWN" at 12243.46,4271.1 h60
  text "X" at 12966.46,4271.1 h60
  text "OTHER" at 13392.46,4128.85 h60
  text "PTH COPPER THICKNESS:" at 11407.91,4125.32 h60
  text "X" at 12547.14,4125.32 h60
  text "20-30 um" at 12675.14,4125.32 h60
  text "BOARD FINISH:" at 11333.46,3977.73 h60
  text "SILKSCREEN:" at 11488.68,3867.6 h60
  text "X" at 12446.46,3867.6 h60
  text "TOP" at 12563.46,3867.6 h60
  text "X" at 12956.46,3867.6 h60
  text "BOTTOM" at 13074.46,3867.6 h60
  text "SILKSCREEN COLOR:" at 11488.68,3712.41 h60
  text "X" at 12445.46,3712.41 h60
  text "WHITE" at 12563.46,3712.41 h60
  text "OTHER" at 13074.46,3712.41 h60
  text "X" at 12576.46,3568.96 h60
  text "GREEN" at 12694.46,3568.96 h60
  text "OTHER" at 13312.46,3568.96 h60
  text "SOLDER RESIST COLOR:" at 11488.68,3562.1 h60
  text "X" at 12576.46,3414.71 h60
  text "MATTE" at 12694.46,3414.71 h60
  text "SEMI-GLOSS" at 13312,3414.07 h60
  text "IMMERSION GOLD (ENIG)" at 12394.46,3241.94 h60
  text "ENEPIG" at 13732,3234.72 h60
  text "SURFACE FINISH:" at 11333.46,3233.72 h60
  text "X" at 12216.46,3233.72 h60
  text "IMM. TIN/SILVER OR EQUIV" at 11663,3096.4 h60
  text "OTHER" at 13094.46,3092.47 h60
  text "ARRAY/PANEL:" at 11333.46,2937.09 h60
  text "CUT AND TRIM PER M1 BOARD OUTLINE" at 12394.46,2928.87 h60
  text "N.C. ROUTE" at 12394.46,2792.9 h60
  text "X" at 13082.46,2792.9 h60
  text "V. SCORE" at 13260.46,2792.9 h60
  text "CERTIFICATION:" at 11333.46,2663.77 h60
  text "MATERIALS AND WORKMANSHIP FOR ALL PCBS" at 12058.46,2663.77 h60
  text "TO MEET OR EXCEED THE REQUIREMENTS OF:" at 12058.46,2569.71 h60
  text "X" at 11695.97,2441.08 h60
  text "ANSI IPC-A-600F CLASS ->" at 11823.96,2441.08 h60
  text "X" at 13471.97,2441.08 h60
  text "2" at 13581.96,2441.08 h60
  text "1" at 13266.96,2439.58 h60
  text "3" at 13935.96,2439.58 h60
  text "X" at 12507.97,2293.39 h60
  text "RoHS" at 12635.96,2293.39 h60
  text "OTHER" at 13280.36,2293.39 h60
  text "PER ORDER" at 13677.42,2293.39 h60
  text "ALL BOARDS MUST MEET OR EXCEED UL94-V0 REQUIREMENTS." at 11361,2139.57 h60
  text "PCB MUST BEAR THE UL94V-0 UL REGISTERED MATERIAL ID NUMBER" at 11361,2023.5 h60
  text "ADDITIONAL REQUIREMENTS:" at 11333.46,1854.08 h60
  text "MICROSECTION:" at 11408.23,1746.95 h60
  text "YES" at 12313.96,1746.95 h60
  text "REQUIRED" at 13175.46,1602.62 h60
  text "BARE BOARD ELEC. TEST:" at 11408.23,1599.76 h60
  text "NONE" at 12713.96,1599.76 h60
  text "X" at 13057.46,1599.76 h60
  text "PER ORDER" at 13767.46,1599.76 h60
  text "XX MIL VIAS REQUIRE NON-CONDUCTIVE FILL AND PLANARIZE" at 11576.38,1394.82 h59
  text "XX MIL VIAS REQUIRE CONDUCTIVE FILL AND PLANARIZE" at 11584.38,1290.84 h60
  text "OUTER XX MIL TRACES REQUIRE 50 OHM SINGLE-ENDED IMPEDANCE" at 11583.39,1127.46 h58
  text "LAYER 2 & 3 (INNER LAYERS) XX MIL WIDE, XX MIL SPACE / TRACES REQUIRE 100 OHM DIFFERENTIAL IMPEDANCE" at 11575.39,891.74 h60
  text ".Layer_Name" at 577,-858.49 h60
M11 Gerber Information:
  lines w10: -292,-930.17 6308,-930.17 ; -292,-726.83 6310,-726.83 ; -292,-523.5 -292,-1133.5 3713,-1133.5 6310,-1133.5 6310,-523.5 -291.5,-523.5 -291.5,-1133.5 1284,-1133.5 ; 2173,-1133.5 2173,-523.5 ; 3440,-726.83 3440,-523.5 ; 4280,-726.83 4280,-523.5 ; 4902,-1140 4902,-937.17
  text "ALL ARTWORK VIEWED FROM TOP SIDE" at -228.5,-655.67 h60
  text "BOARD #:" at 2248,-655.67 h60
  text ".PRJ_Number" at 2793.5,-655.67 h60
  text "REV:" at 3638,-655.67 h60
  text ".PCB_Rev" at 3929.5,-655.67 h60
  text "SVN REV:" at 4476,-655.67 h60
  text ".VersionControl_RevNumber" at 4982,-655.67 h60
  text "LAYER NAME =" at -228.5,-858.49 h60
  text "TID #:" at 2248,-859 h60
  text ".TID" at 2793.5,-859 h60
  text "PLOT NAME =" at -228.5,-1064.34 h60
  text ".plot_File_Name" at 577,-1064.34 h60
  text "GENERATED    :" at 2250,-1064.34 h60
  text ".Print_Date" at 3119.5,-1064.34 h60
  text ".Print_Time" at 3848.5,-1064.34 h60
  text "TEXAS INSTRUMENTS" at 5113,-1064.34 h60
M12 Stackup:
  drawing of 295 lines, arcs and shapes, not listed
  text "Layer" at 9821.59,7874.94 h60
  text "Name" at 10231.51,7874.94 h60
  text "Material" at 11161.25,7874.94 h60
  text "Thickness" at 12021.02,7874.94 h60
  text "Constant" at 12670.85,7874.94 h60
  text "Board Layer Stack" at 13240.71,7874.94 h60
  text "Top Overlay" at 10231.51,7754.94 h60
  text "Top Solder" at 10231.51,7634.94 h60
  text "Solder Resist" at 11161.25,7634.94 h60
  text "0.40mil" at 12021.02,7634.94 h60
  text "3.5" at 12670.85,7634.94 h60
  text "1" at 9821.59,7514.94 h60
  text "Top Layer" at 10231.51,7514.94 h60
  text "1.40mil" at 12021.02,7514.94 h60
  text "Dielectric 1" at 10231.51,7394.94 h60
  text "PP-006" at 11161.25,7394.94 h60
  text "2.80mil" at 12021.02,7394.94 h60
  text "4.1" at 12670.85,7394.94 h60
  text "2" at 9821.59,7274.94 h60
  text "GND Plane" at 10231.51,7274.94 h60
  text "CF-004" at 11161.25,7274.94 h60
  text "1.38mil" at 12021.02,7274.94 h60
  text "Dielectric1" at 10231.51,7154.94 h60
  text "FR-4 High Tg" at 11161.25,7154.94 h60
  text "59.20mil" at 12021.02,7154.94 h60
  text "4.8" at 12670.85,7154.94 h60
  text "3" at 9821.59,7034.94 h60
  text "Power Plane" at 10231.51,7034.94 h60
  text "CF-004" at 11161.25,7034.94 h60
  text "1.38mil" at 12021.02,7034.94 h60
  text "Dielectric 2" at 10231.51,6914.94 h60
  text "PP-006" at 11161.25,6914.94 h60
  text "2.80mil" at 12021.02,6914.94 h60
  text "4.1" at 12670.85,6914.94 h60
  text "4" at 9821.59,6794.94 h60
  text "Bottom Layer" at 10231.51,6794.94 h60
  text "1.40mil" at 12021.02,6794.94 h60
  text "Bottom Solder" at 10231.51,6674.94 h60
  text "Solder Resist" at 11161.25,6674.94 h60
  text "0.40mil" at 12021.02,6674.94 h60
  text "3.5" at 12670.85,6674.94 h60
  text "Bottom Overlay" at 10231.51,6554.94 h60
  text ".Layer_Name" at 577,-858.49 h60
M13 Component Bodies Top:
  text ".Layer_Name" at 577,-858.49 h60
M14 Component Bodies Bottom:
  text ".Layer_Name" at 577,-858.49 h60
M15 Courtyards Top:
  text ".Layer_Name" at 577,-858.49 h60
M16 Courtyards Bottom:
  text ".Layer_Name" at 577,-858.49 h60
Drill Drawing:
  circle w10: c5363.76,2917 r16.59
  circle w10: c5363.76,2917 r27.64
  circle w10: c5363.76,1797.47 r27.64
  lines w10: 5336.12,1949.51 5391.4,1949.51 5363.76,1894.22 5336.12,1949.51 ; 5336.12,2046.26 5363.76,2018.61 5391.4,2046.26 5363.76,2073.9 5336.12,2046.26 ; 5336.12,2143.01 5391.4,2143.01 5391.4,2198.29 5336.12,2198.29 5336.12,2143.01 ; 5336.12,2267.4 5363.76,2281.22 5391.4,2267.4 5377.58,2295.04 5391.4,2322.68 5363.76,2308.86 5336.12,2322.68 5349.94,2295.04 5336.12,2267.4 ; 5336.12,2447.07 5391.4,2447.07 5363.76,2391.79 5336.12,2447.07 ; 5336.12,2530 5349.94,2530 5349.94,2516.18 5377.58,2516.18 5377.58,2530 5391.4,2530 5391.4,2557.65 5377.58,2557.65 5377.58,2571.47 5349.94,2571.47 5349.94,2557.65 5336.12,2557.65 5336.12,2530 ; 5336.12,2640.57 5336.12,2654.39 5349.94,2668.22 5336.12,2682.04 5336.12,2695.86 5349.94,2695.86 5363.76,2682.04 5377.58,2695.86 5391.4,2695.86 5391.4,2682.04 5377.58,2668.22 5391.4,2654.39 5391.4,2640.57 5377.58,2640.57 5363.76,2654.39 5349.94,2640.57 5336.12,2640.57 ; 5336.12,2778.79 5349.94,2778.79 5363.76,2764.97 5377.58,2778.79 5391.4,2778.79 5377.58,2792.61 5391.4,2806.43 5377.58,2806.43 5363.76,2820.25 5349.94,2806.43 5336.12,2806.43 5349.94,2792.61 5336.12,2778.79 ; 5336.12,3027.57 5349.94,3027.57 5363.76,3013.75 5377.58,3027.57 5391.4,3027.57 5377.58,3041.39 5391.4,3055.21 5377.58,3055.21 5363.76,3069.03 5349.94,3055.21 5336.12,3055.21 5349.94,3041.39 5336.12,3027.57 ; 5336.12,3138.14 5391.4,3138.14 5391.4,3193.43 5336.12,3193.43 5336.12,3138.14 ; 5336.12,3262.53 5363.76,3276.35 5391.4,3262.53 5377.58,3290.18 5391.4,3317.82 5363.76,3304 5336.12,3317.82 5349.94,3290.18 5336.12,3262.53 ; 5347.17,2436.02 5380.35,2436.02 5363.76,2402.85 5347.17,2436.02 ; 5347.17,3033.1 5355.47,3033.1 5363.76,3024.81 5372.05,3033.1 5380.35,3033.1 5372.05,3041.39 5380.35,3049.69 5372.05,3049.69 5363.76,3057.98 5355.47,3049.69 5347.17,3049.69 5355.47,3041.39 5347.17,3033.1 ; 5347.17,3149.2 5380.35,3149.2 5380.35,3182.37 5347.17,3182.37 5347.17,3149.2 ; 5347.17,3273.59 5363.76,3281.88 5380.35,3273.59 5372.05,3290.18 5380.35,3306.76 5363.76,3298.47 5347.17,3306.76 5355.47,3290.18 5347.17,3273.59
  lines w12: 5286,1732.51 8516.34,1732.51 ; 5286,3349.61 8516.34,3349.61 ; 5623.7,1608.12 5623.7,3474 ; 5955.55,1608.12 5955.55,3474 ; 6591.67,1608.12 6591.67,3474 ; 6850.72,1608.12 6850.72,3474 ; 7225.68,1608.12 7225.68,3474 ; 7950.16,1608.12 7950.16,3474 ; 5286,1608.12 8516.34,1608.12 8516.34,3474 5286,3474 5286,1608.12
  text "Symbol" at 5360.64,3386.93 h72
  text "Quantity" at 5661.02,3386.93 h72
  text "Finished Hole Size" at 5992.87,3386.93 h72
  text "Plated" at 6628.99,3386.93 h72
  text "Hole Type" at 6888.04,3386.93 h72
  text "Drill Layer Pair" at 7263,3386.93 h72
  text "Hole Tolerance" at 7987.48,3386.93 h72
  text "608" at 5661.02,3262.53 h60
  text "6.00mil (0.152mm)" at 5992.87,3262.53 h60
  text "PTH" at 6628.99,3262.53 h60
  text "Round" at 6888.04,3262.53 h60
  text "Top Layer - Bottom Layer" at 7263,3262.53 h60
  text "35" at 5661.02,3138.14 h60
  text "7.87mil (0.200mm)" at 5992.87,3138.14 h60
  text "PTH" at 6628.99,3138.14 h60
  text "Round" at 6888.04,3138.14 h60
  text "Top Layer - Bottom Layer" at 7263,3138.14 h60
  text "204" at 5661.02,3013.75 h60
  text "8.00mil (0.203mm)" at 5992.87,3013.75 h60
  text "PTH" at 6628.99,3013.75 h60
  text "Round" at 6888.04,3013.75 h60
  text "Top Layer - Bottom Layer" at 7263,3013.75 h60
  text "7" at 5661.02,2889.36 h60
  text "12.99mil (0.330mm)" at 5992.87,2889.36 h60
  text "PTH" at 6628.99,2889.36 h60
  text "Round" at 6888.04,2889.36 h60
  text "Top Layer - Bottom Layer" at 7263,2889.36 h60
  text "3" at 5661.02,2764.97 h60
  text "35.43mil (0.900mm)" at 5992.87,2764.97 h60
  text "PTH" at 6628.99,2764.97 h60
  text "Round" at 6888.04,2764.97 h60
  text "Top Layer - Bottom Layer" at 7263,2764.97 h60
  text "12" at 5661.02,2640.57 h60
  text "40.00mil (1.016mm)" at 5992.87,2640.57 h60
  text "PTH" at 6628.99,2640.57 h60
  text "Round" at 6888.04,2640.57 h60
  text "Top Layer - Bottom Layer" at 7263,2640.57 h60
  text "40" at 5661.02,2516.18 h60
  text "45.28mil (1.150mm)" at 5992.87,2516.18 h60
  text "PTH" at 6628.99,2516.18 h60
  text "Round" at 6888.04,2516.18 h60
  text "Top Layer - Bottom Layer" at 7263,2516.18 h60
  text "5" at 5661.02,2391.79 h60
  text "47.24mil (1.200mm)" at 5992.87,2391.79 h60
  text "PTH" at 6628.99,2391.79 h60
  text "Round" at 6888.04,2391.79 h60
  text "Top Layer - Bottom Layer" at 7263,2391.79 h60
  text "3" at 5661.02,2267.4 h60
  text "50.00mil (1.270mm)" at 5992.87,2267.4 h60
  text "PTH" at 6628.99,2267.4 h60
  text "Round" at 6888.04,2267.4 h60
  text "Top Layer - Bottom Layer" at 7263,2267.4 h60
  text "11" at 5661.02,2143.01 h60
  text "51.18mil (1.300mm)" at 5992.87,2143.01 h60
  text "PTH" at 6628.99,2143.01 h60
  text "Round" at 6888.04,2143.01 h60
  text "Top Layer - Bottom Layer" at 7263,2143.01 h60
  text "11" at 5661.02,2018.61 h60
  text "63.00mil (1.600mm)" at 5992.87,2018.61 h60
  text "PTH" at 6628.99,2018.61 h60
  text "Round" at 6888.04,2018.61 h60
  text "Top Layer - Bottom Layer" at 7263,2018.61 h60
  text "3" at 5661.02,1894.22 h60
  text "72.84mil (1.850mm)" at 5992.87,1894.22 h60
  text "PTH" at 6628.99,1894.22 h60
  text "Round" at 6888.04,1894.22 h60
  text "Top Layer - Bottom Layer" at 7263,1894.22 h60
  text "4" at 5661.02,1769.83 h60
  text "125.98mil (3.200mm)" at 5992.87,1769.83 h60
  text "PTH" at 6628.99,1769.83 h60
  text "Round" at 6888.04,1769.83 h60
  text "Top Layer - Bottom Layer" at 7263,1769.83 h60
  text "946 Total" at 5661.02,1645.44 h60
  text ".Layer_Name" at 577,-858.49 h60
M17 Embedded Cavity:
  text ".Layer_Name" at 577,-858.49 h60
M18 Embedded Assembly:
  text ".Layer_Name" at 577,-858.49 h60
M19 Embedded Keepout:
  text ".Layer_Name" at 577,-858.49 h60

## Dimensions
0,-400 to 1000,-400 on M2 Board Dimensions
0,0 to 4586.61,0 on M2 Board Dimensions
0,0 to 0,2962.6 on M2 Board Dimensions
